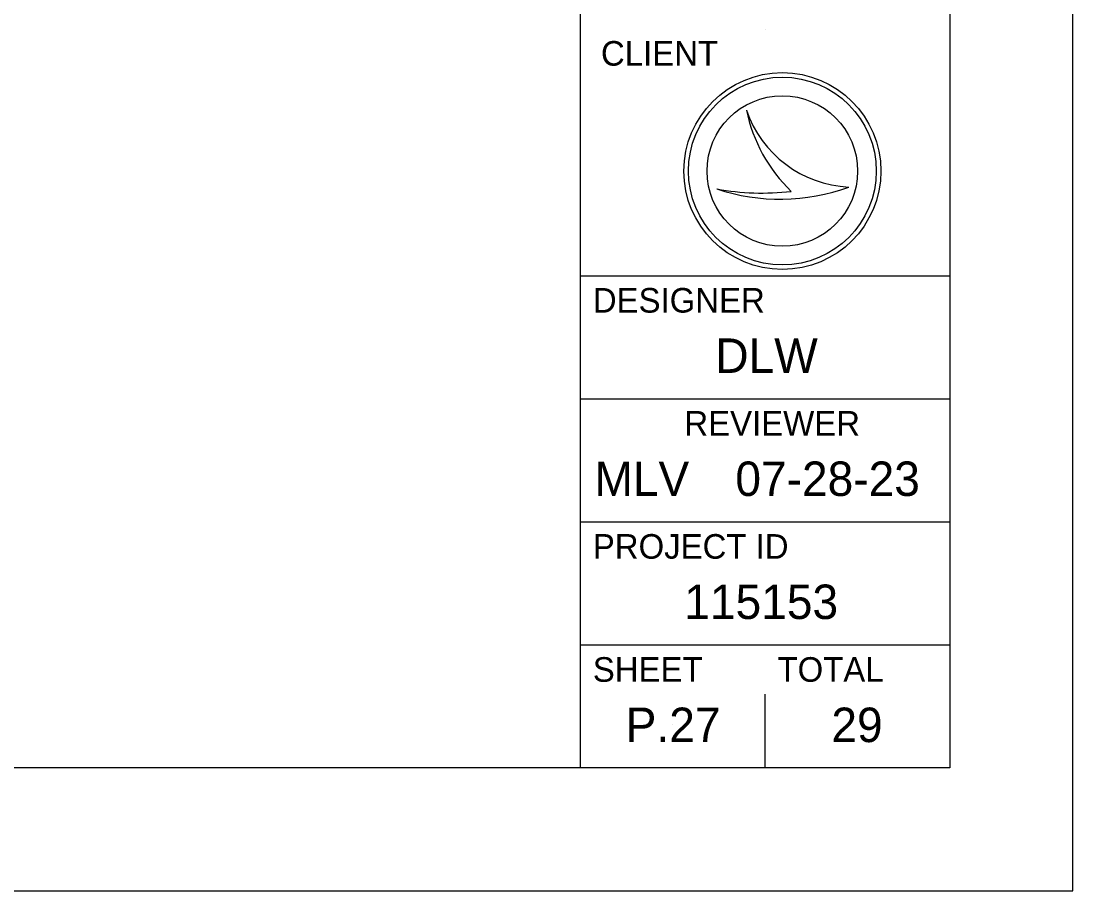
# Model space of a CAD drawing. Extents: x 0 to 680, y 0 to 551.
# Drawn here: x 594.6 to 680, y 0 to 70.7 of the extents above; entities that cross this region are included whole.
import ezdxf

# ---------------------------------------------------------------- set-up
doc = ezdxf.new("R2010")
doc.units = 0
for name, color, linetype in [('SH_Border', 7, 'Continuous'), ('SH_Cut_Line', 7, 'Continuous'), ('SH_Data', 7, 'Continuous'), ('SH_Text', 7, 'Continuous')]:
    doc.layers.add(name, color=color, linetype=linetype)

msp = doc.modelspace()

# ---------------------------------------------------------------- linework, layer by layer
at = {"layer": 'SH_Border'}
for p, q in [((640, 10), (640, 430)), ((640, 50), (670, 50)), ((640, 40), (670, 40)), ((640, 30), (670, 30)), ((640, 20), (670, 20))]:
    msp.add_line(p, q, dxfattribs=at)
msp.add_lwpolyline([(30, 430), (670, 430), (670, 10), (30, 10)], close=True, dxfattribs=at)
at = {"layer": 'SH_Cut_Line'}
msp.add_lwpolyline([(0, 0), (680, 0), (680, 440), (0, 440)], close=True, dxfattribs=at)
at = {"layer": 'SH_Data'}
for p, q in [((655, 70), (655, 70)), ((653.474, 63.456), (653.474, 63.456)), ((651.07, 57.055), (651.07, 57.056)), ((661.791, 57.199), (661.792, 57.199)), ((655, 10), (655, 16)), ((647.5, 13.5), (647.5, 13.5))]:
    msp.add_line(p, q, dxfattribs=at)
for radius in [8, 7.629, 7.629, 6.116]:
    msp.add_circle((656.395, 58.503), radius, dxfattribs=at)
for centre, radius, start, end in [((662.25, 66.466), 9.277, 198.92567, 198.93195), ((665.942, 66.024), 12.729, 191.63793, 191.64215), ((662.25, 66.466), 9.277, 198.93195, 267.16574), ((665.942, 66.024), 12.729, 191.64215, 226.09467), ((656.226, 72.423), 16.21, 251.45274, 251.45764), ((654.763, 76.973), 20.257, 259.49639, 259.49952), ((656.226, 72.423), 16.21, 251.45764, 290.08324), ((654.763, 76.973), 20.257, 259.49952, 276.66723)]:
    msp.add_arc(centre, radius, start, end, dxfattribs=at)

# ---------------------------------------------------------------- texts
for s, height, p in [('DESIGNER', 2, (641, 47)), ('DLW', 2.8, (650.949, 42.1)), ('REVIEWER', 2, (648.437, 37)), ('MLV', 2.8, (641.13, 32.1)), ('07-28-23', 2.8, (652.578, 32.1)), ('PROJECT ID', 2, (641, 27)), ('115153', 2.8, (648.43, 22.1)), ('SHEET', 2, (641, 17)), ('TOTAL', 2, (656, 17)), ('P.27', 2.8, (643.669, 12.1)), ('29', 2.8, (660.377, 12.1))]:
    msp.add_text(s, height=height, dxfattribs=at).set_placement(p)
at = {"layer": 'SH_Text'}
msp.add_text('CLIENT', height=2, dxfattribs=at).set_placement((641.662, 67.068))

doc.saveas('drawing.dxf')
